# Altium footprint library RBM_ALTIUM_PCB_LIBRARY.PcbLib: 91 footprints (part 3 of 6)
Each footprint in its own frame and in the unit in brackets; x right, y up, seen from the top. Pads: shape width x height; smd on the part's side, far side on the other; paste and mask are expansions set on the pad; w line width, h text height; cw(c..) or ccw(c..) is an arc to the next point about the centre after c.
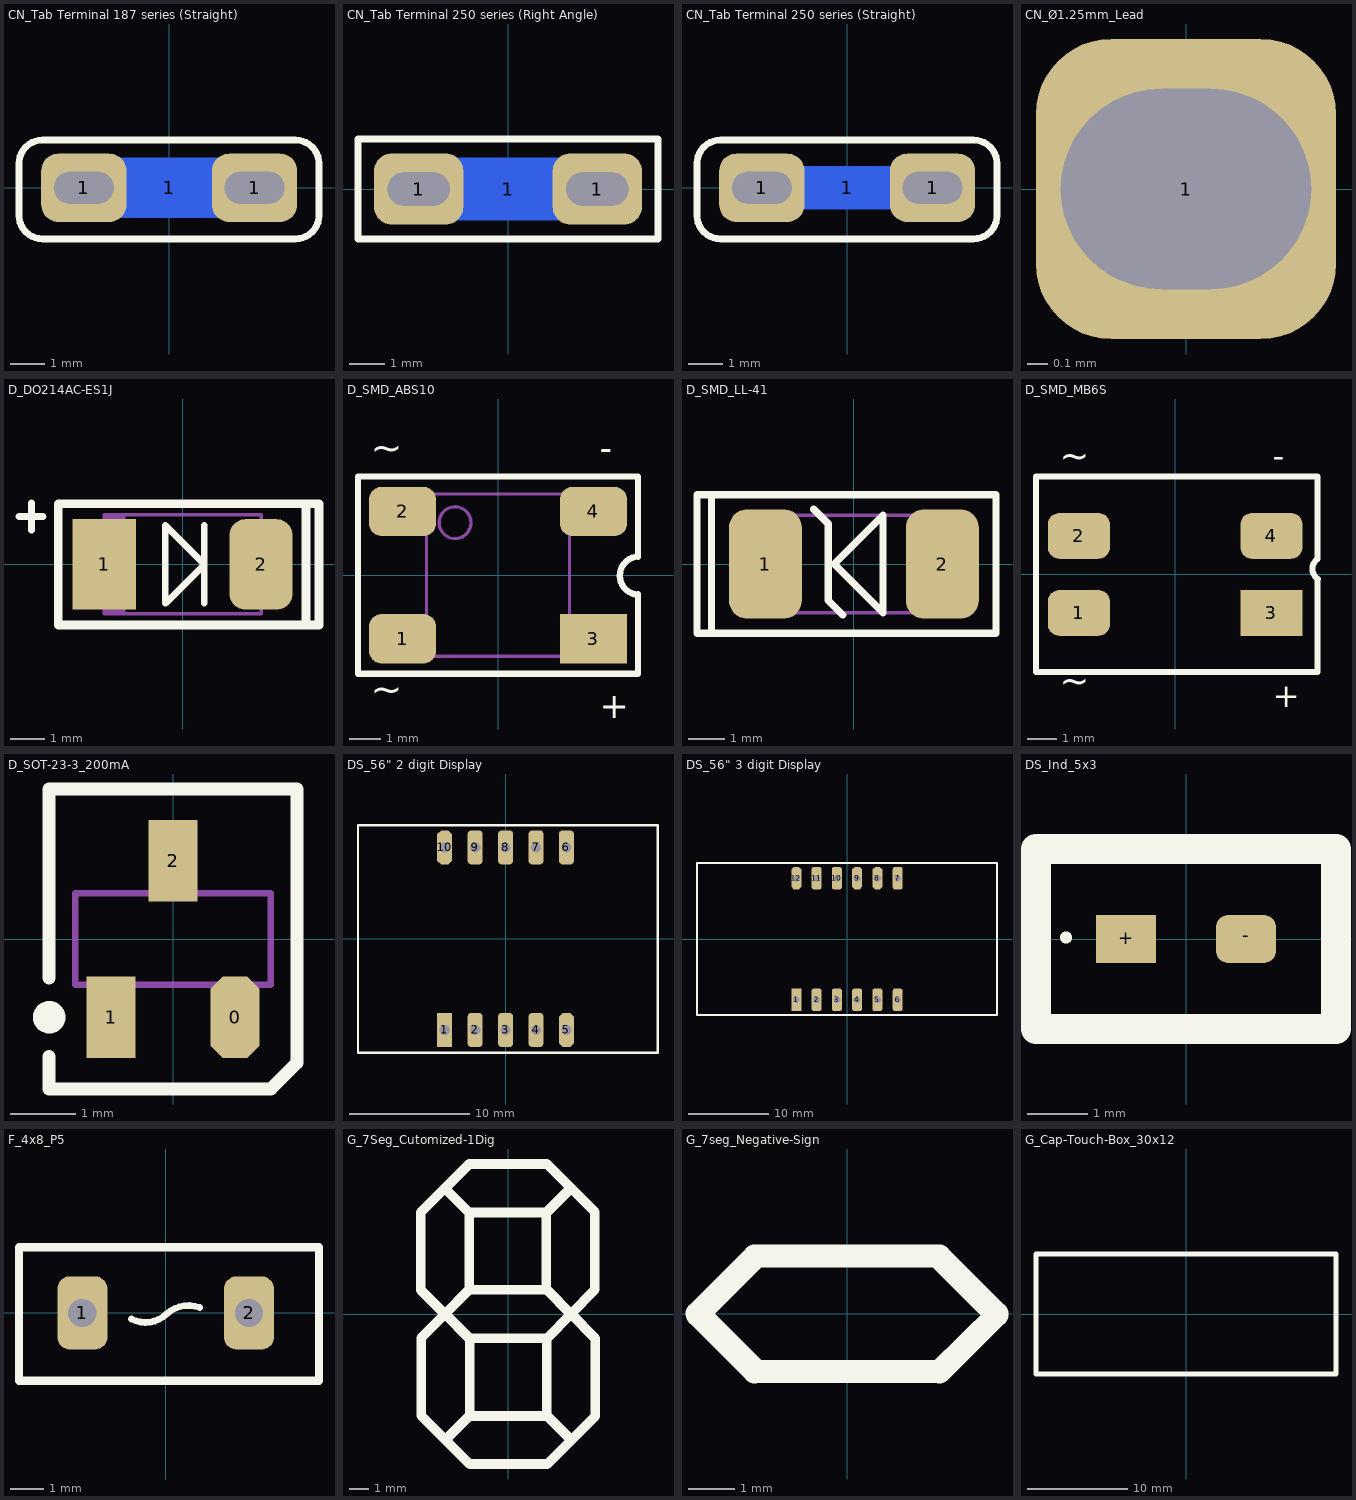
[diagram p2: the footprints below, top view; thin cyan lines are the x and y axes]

## CN_Tab Terminal 187 series (Straight) [mm]
pads (3):
  rrect50% 2.5x2 hole 0.95 slot 1.75 at 0 deg: 1(-2.5,0) 1(2.5,0)
  rect 2.85x1.75 smd far side: 1(0,0)
Top Overlay:
  lines w0.2: -4.4,-0.81 ccw(c-3.712,-0.81) -3.712,-1.498 3.7,-1.497 ccw(c3.7,-0.81) 4.388,-0.81 ; -4.4,-0.8 -4.4,0.712 ; -4.4,0.71 cw(c-3.712,0.71) -3.712,1.398 ; -3.712,1.397 3.7,1.397 ; 3.7,1.398 cw(c3.7,0.71) 4.388,0.71 ; 4.388,-0.812 4.388,0.7
3D body "4.8mm PCB Tab Terminal (Straight).stp": height 9, standoff -3.45, extent -3.962,-1.3 3.962,1.494

## CN_Tab Terminal 250 series (Right Angle) [mm]
pads (3):
  rrect50% 2.5x2 hole 0.95 slot 1.75 at 0 deg: 1(-2.5,0) 1(2.5,0)
  rect 2.85x1.75 smd far side: 1(0,0)
Top Overlay:
  lines w0.2: -4.2,-1.397 4.2,-1.397 4.2,1.397 -4.2,1.397 -4.2,-1.397
3D body "6.3mm PCB Tab Terminal (Right Angle).STEP": height 9.1, standoff -2.9, extent -4,-0.4 12.2,0.4

## CN_Tab Terminal 250 series (Straight) [mm]
pads (3):
  rrect50% 2.5x2 hole 0.95 slot 1.75 at 0 deg: 1(-2.5,0) 1(2.5,0)
  rect 2.85x1.25 smd far side: 1(0,0)
Top Overlay:
  lines w0.2: -4.4,-0.81 ccw(c-3.712,-0.81) -3.712,-1.498 3.7,-1.497 ccw(c3.7,-0.81) 4.388,-0.81 ; -4.4,-0.8 -4.4,0.712 ; -4.4,0.71 cw(c-3.712,0.71) -3.712,1.398 ; -3.712,1.397 3.7,1.397 ; 3.7,1.398 cw(c3.7,0.71) 4.388,0.71 ; 4.388,-0.812 4.388,0.7
3D body "6.3mm PCB Tab Terminal (Straight).stp": height 10.2, standoff -3.8, extent -4,-0.4 4,0.4

## CN_Ø1.25mm_Lead [mm] "Lead Wire"
pads (1):
  rrect50% 1.5x1.5 / inner rrect50% 1.5x1.5 / far side rrect50% 2.5x1.5 hole 1.25 slot 1 at 90 deg: 1(0,0)

## D_DO214AC-ES1J [mm] "Molded Diode, 2-Leads, Body 4.29x2.69mm, IPC Medium Density"
height 2.44
pads (2):
  rect 1.85x2.65 smd: 1(-2.3,0)
  rrect50% 1.85x2.65 smd: 2(2.3,0)
Top Overlay:
  lines w0.2: -4.8,1.4 -4.1,1.4 ; -4.435,1 -4.435,1.8 ; 0.635,-1.143 0.635,1.143 ; -0.508,-1.143 -0.508,1.143 0.635,0 -0.508,-1.143
  lines w0.254: 3.619,-1.778 3.619,1.778 ; -3.65,-1.778 -3.65,1.778 4,1.778 4,-1.778 -3.65,-1.778
Mechanical 13:
  rectangle: -2.3,-1.45 -1.681,1.45
  lines w0.1: -2.3,-1.45 -2.3,1.45 2.3,1.45 2.3,-1.45 -2.3,-1.45
3D body "DIOM4327X24N.step": height 2.44, standoff 0, extent -2.52,-1.45 2.52,1.45

## D_SMD_ABS10 [mm]
pads (4):
  rrect50% 2.1x1.55 smd: 1(-3,-2) 2(-3,2) 4(3,2)
  rect 2.1x1.55 smd: 3(3,-2)
Top Overlay:
  lines w0.2: 4.299,-0.603 cw(c4.427,-0.017) 4.306,0.57 ; 4.4,-0.603 4.4,-3.1 -4.4,-3.1 -4.4,3.1 4.4,3.1 4.4,0.57
  text "~" at -4,3.3 h1.5
  text "+" at 3.2,-3.8 h0.8
  text "-" at 3.2,4.2 h0.8
  text "~" at -4,-4.3 h1.5
Mechanical 13:
  circle w0.1: c-1.35,1.65 r0.5
  lines w0.1: -2.25,-2.55 2.25,-2.55 2.25,2.55 -2.25,2.55 -2.25,-2.55
3D body "TSOP400P650X160-4N.step": height 1.6, standoff 0, extent -3.25,-2.55 3.25,2.55

## D_SMD_LL-41 [mm]
height 2.67
pads (2):
  rrect50% 2x3 smd: 1(-2.425,0) 2(2.425,0)
Top Overlay:
  lines w0.2: -3.9,-1.8 -3.9,1.8 ; -1.1,1.5 -0.7,1.1 -0.7,-1 -0.3,-1.4 ; -4.3,-1.9 -4.3,1.9 3.9,1.9 3.9,-1.9 -4.3,-1.9 ; -0.535,0 0.8,-1.335 0.8,1.335 -0.535,0
Mechanical 13:
  lines w0.1: -2.75,-1.335 2.75,-1.335 2.75,1.335 -2.75,1.335 -2.75,-1.335
3D body "ZD.step": height 2.46, standoff 0.01, extent -2.575,-1.227 2.575,1.228

## D_SMD_MB6S [mm]
pads (4):
  rrect50% 2.1x1.55 smd: 1(-3.25,-1.3) 2(-3.25,1.3) 4(3.25,1.3)
  rect 2.1x1.55 smd: 3(3.25,-1.3)
Top Overlay:
  lines w0.2: 4.8,-0.153 4.8,-3.3 -4.7,-3.3 -4.7,3.3 4.8,3.3 4.8,0.523 ; 4.813,0.523 ccw(c5.028,0.186) 4.816,-0.153
  text "~" at -3.9,3.3 h1.5
  text "+" at 3.3,-3.8 h0.8
  text "-" at 3.3,4.2 h0.8
  text "~" at -3.9,-4.3 h1.5
3D body "User Library-moste3k.STEP": height 1.45, standoff -0.08, extent -3.447,-2.417 3.453,2.577

## D_SOT-23-3_200mA [mm] "Diodes - General Purpose 100V 200mA 1.25V @ 200mA SOT-23(SOT-23-3) RoHS"
height 1.15
pads (3):
  oct 0.75x1.25 smd: 0(0.95,-1.2)
  rect 0.75x1.25 smd: 1(-0.95,-1.2) 2(0,1.2)
Top Overlay:
  circle w0.25: c-1.9,-1.2 r0.125
  lines w0.2: -1.9,-1.8 -1.9,-2.3 1.5,-2.3 1.9,-1.9 1.9,2.3 -1.9,2.3 -1.9,-0.6
Mechanical 13:
  lines w0.1: -1.5,-0.7 1.5,-0.7 1.5,0.7 -1.5,0.7 -1.5,-0.7
3D body "SOT95P245X115-3N.step": height 1.15, standoff 0, extent -1.5,-1.3 1.5,1.3

## DS_56" 2 digit Display [mm]
pads (10):
  rect 1.25x2.85 hole 0.85: 1(-5.08,-7.62)
  rrect50% 1.25x2.85 hole 0.85: 2(-2.54,-7.62) 3(0,-7.62) 4(2.54,-7.62) 6(5.08,7.62) 7(2.54,7.62) 8(0,7.62) 9(-2.54,7.62)
  oct 1.25x2.85 hole 0.85: 5(5.08,-7.62) 10(-5.08,7.62)
Top Overlay:
  lines w0.2: -12.319,-9.525 -12.319,9.475 12.7,9.475 12.7,-9.525 ; -12.28,-9.525 12.72,-9.525
Bottom Overlay:
  text "d" at -4.878,-4.833 h1
  text "dp" at -1.738,-4.9 h1
  text "e" at 0.201,-4.833 h1
  text "c" at 2.742,-4.833 h1
  text "g" at -2.24,4.3 h1
  text "f" at 0.301,4.167 h1
  text "b" at 5.38,4.167 h1
  text "a" at 2.9,4.167 h1
  text "D1" at -4.4,4.1 h1
  text "D2" at 5.8,-5 h1
3D body: height 7, standoff 1, extent -12.3,-9.313 12.719,9.61
3D body: height 7, standoff 1, extent -12.319,-9.525 12.7,9.398
3D body: height 3, standoff -3, extent -2.798,-7.879 -2.28,-7.36
3D body: height 3, standoff -3, extent -0.258,-7.879 0.26,-7.36
3D body: height 3, standoff -3, extent 2.282,-7.879 2.8,-7.36
3D body: height 3, standoff -3, extent 4.822,-7.879 5.34,-7.36
3D body: height 3, standoff -3, extent -5.338,-7.879 -4.82,-7.36
3D body: height 3, standoff -3, extent 4.822,7.361 5.34,7.88
3D body: height 3, standoff -3, extent 2.282,7.361 2.8,7.88
3D body: height 3, standoff -3, extent -0.258,7.361 0.26,7.88
3D body: height 3, standoff -3, extent -2.798,7.361 -2.28,7.88
3D body: height 3, standoff -3, extent -5.338,7.361 -4.82,7.88

## DS_56" 3 digit Display [mm]
pads (12):
  rect 1.25x2.85 hole 0.85: 1(-6.35,-7.62)
  rrect50% 1.25x2.85 hole 0.85: 2(-3.81,-7.62) 3(-1.27,-7.62) 4(1.27,-7.62) 5(3.81,-7.62) 6(6.35,-7.62) 7(6.35,7.62) 10(-1.27,7.62) 11(-3.81,7.62)
  oct 1.25x2.85 hole 0.85: 8(3.81,7.62) 9(1.27,7.62) 12(-6.35,7.62)
Top Overlay:
  lines w0.2: -18.796,-9.525 18.796,-9.525 18.796,9.525 -18.796,9.525 -18.796,-9.525
Bottom Overlay:
  text "a" at -3.37,4.3 h1
  text "b" at 6.73,4.2 h1
  text "f" at -1.07,4.3 h1
  text "g" at 4.1,-4.567 h1
  text "c" at 1.6,-4.7 h1
  text "e" at -6.1,-4.767 h1
  text "dp" at -0.5,-4.7 h1
  text "d" at -3.5,-4.8 h1
  text "D3" at 4.64,4.2 h1
  text "D2" at 2.13,4.2 h1
  text "D1" at -5.67,4.2 h1
3D body "User Library-5631_w_o_color_jam.step": height 8.1, standoff -5.5, extent -18.796,-9.525 18.804,9.475

## DS_Ind_5x3 [mm]
pads (2):
  rect 1x0.8 smd: +(-1,0)
  rrect50% 1x0.8 smd: -(1,0)
Top Overlay:
  circle w0.1: c-2,0.025 r0.05
  lines w0.5: -2.5,-1.5 2.5,-1.5 2.5,1.5 -2.5,1.5 -2.5,-1.5
3D body "ALSRobot-LED0603(R).step": height 0.6, standoff 0, extent -0.81,-0.4 0.81,0.4

## F_4x8_P5 [mm]
pads (2):
  rrect50% 1.5x2.2 hole 0.85: 1(-2.5,0) 2(2.5,0)
Top Overlay:
  lines w0.2: -1.028,-0.184 ccw(c-0.609,0.633) 0.034,-0.022 ; 0.001,-0.057 cw(c0.685,-0.753) 1.023,0.162
  lines w0.254: -4.402,-2.032 4.598,-2.032 4.598,1.968 -4.402,1.968 -4.402,-2.032
3D body: height 7, standoff 0.68, extent -4.505,-1.968 4.512,1.968
3D body: height 1.5, standoff -2, extent -2.797,-0.299 -2.199,0.3
3D body: height 1.5, standoff -2, extent 2.203,-0.299 2.801,0.3

## G_7Seg_Cutomized-1Dig [mm]
Top Overlay:
  lines w0.5: -4.475,1.237 -3.237,0 ; -3.263,0 -4.5,1.237 -4.5,5.237 -3.263,6.475 ; -3.237,6.5 -2,7.737 2,7.737 3.237,6.5 4.475,5.263 4.475,1.263 3.237,0.025 ; -3.212,-6.475 -1.975,-5.237 2.025,-5.237 3.263,-6.475 ; -3.212,-6.45 -1.975,-5.212 -1.975,-1.212 -3.212,0.025 ; -2,-7.687 -3.237,-6.45 -4.475,-5.212 -4.475,-1.212 -3.237,0.025 ; -2,-1.212 -3.237,0.025 ; -2,7.712 -3.237,6.475 ; -1.975,-7.712 2.025,-7.712 3.263,-6.475 ; 3.212,0.025 1.975,1.263 1.975,5.263 3.212,6.5 ; 3.237,-6.475 2,-5.237 2,-1.237 ; 3.237,6.475 2,5.237 -2,5.237 ; 3.263,0 4.5,-1.237 4.5,-5.237 3.263,-6.475 ; 4.475,-1.237 3.237,0 ; -3.237,0 -2,1.237 ; -3.237,0 -2,1.237 ; -3.237,0 -2,-1.237 2,-1.237 ; -3.237,0.025 -2,1.263 2,1.263 ; -3.237,6.475 -2,5.237 ; -3.237,6.475 -2,5.237 ; -2,1.237 -2,5.237 ; 2,-1.237 3.237,0 ; 2,-1.237 3.237,0 ; 2,1.263 3.237,0.025 ; 2,1.263 3.237,0.025
3D body: height 8, standoff 0, extent -2.238,7.5 2.25,8
3D body: height 8, standoff 0, extent -3.497,5.003 -1.753,6.747
3D body: height 8, standoff 0, extent -2.238,5 2.25,5.5
3D body: height 8, standoff 0, extent -3.492,6.243 -1.748,7.987
3D body: height 8, standoff 0, extent 1.772,6.235 3.515,7.978
3D body: height 8, standoff 0, extent 1.767,4.994 3.511,6.738
3D body: height 8, standoff 0, extent -4.756,0.962 -4.256,5.45
3D body: height 8, standoff 0, extent -3.503,-0.297 -1.759,1.447
3D body: height 8, standoff 0, extent -2.256,0.962 -1.756,5.45
3D body: height 8, standoff 0, extent -4.743,-0.292 -2.999,1.452
3D body: height 8, standoff 0, extent -4.735,4.972 -2.991,6.715
3D body: height 8, standoff 0, extent -3.494,4.967 -1.75,6.711
3D body: height 8, standoff 0, extent -4.728,-5.438 -4.228,-0.95
3D body: height 8, standoff 0, extent -3.475,-6.697 -1.731,-4.953
3D body: height 8, standoff 0, extent -2.228,-5.438 -1.728,-0.95
3D body: height 8, standoff 0, extent -4.715,-6.692 -2.971,-4.948
3D body: height 8, standoff 0, extent -4.706,-1.428 -2.963,0.315
3D body: height 8, standoff 0, extent -3.466,-1.433 -1.722,0.311
3D body: height 8, standoff 0, extent -2.232,-5.45 2.256,-4.95
3D body: height 8, standoff 0, extent -3.49,-7.947 -1.747,-6.203
3D body: height 8, standoff 0, extent -2.232,-7.95 2.256,-7.45
3D body: height 8, standoff 0, extent -3.486,-6.707 -1.742,-4.963
3D body: height 8, standoff 0, extent 1.778,-6.715 3.522,-4.971
3D body: height 8, standoff 0, extent 1.773,-7.956 3.517,-6.212
3D body: height 8, standoff 0, extent 4.263,-5.45 4.763,-0.962
3D body: height 8, standoff 0, extent 1.765,-1.447 3.509,0.297
3D body: height 8, standoff 0, extent 1.763,-5.45 2.263,-0.962
3D body: height 8, standoff 0, extent 3.006,-1.452 4.749,0.292
3D body: height 8, standoff 0, extent 2.997,-6.715 4.741,-4.972
3D body: height 8, standoff 0, extent 1.757,-6.711 3.501,-4.967
3D body: height 8, standoff 0, extent 4.265,0.956 4.765,5.444
3D body: height 8, standoff 0, extent 1.768,4.959 3.511,6.703
3D body: height 8, standoff 0, extent 1.765,0.956 2.265,5.444
3D body: height 8, standoff 0, extent 3.008,4.954 4.752,6.698
3D body: height 8, standoff 0, extent 3,-0.309 4.743,1.435
3D body: height 8, standoff 0, extent 1.759,-0.305 3.503,1.439
3D body: height 8, standoff 0, extent -2.25,-1.5 2.238,-1
3D body: height 8, standoff 0, extent 1.753,-0.247 3.497,1.497
3D body: height 8, standoff 0, extent -2.25,1 2.238,1.5
3D body: height 8, standoff 0, extent 1.748,-1.487 3.492,0.257
3D body: height 8, standoff 0, extent -3.515,-1.478 -1.772,0.265
3D body: height 8, standoff 0, extent -3.511,-0.238 -1.767,1.506

## G_7seg_Negative-Sign [mm]
Top Overlay:
  lines w0.5: -3.237,0 -2,1.237 ; -3.212,0 -1.975,-1.237 ; -2,-1.263 -3.237,-0.025 -2,1.212 ; 1.975,1.237 3.212,0 ; 2,-1.263 3.25,-0.025 ; 2,-1.25 -2,-1.25 -3.25,0 -2,1.25 2,1.25 3.25,0 ; 2,1.237 3.237,0
3D body: height 8, standoff 0, extent 1.767,-1.506 3.511,0.238
3D body: height 8, standoff 0, extent 1.772,-0.265 3.515,1.478
3D body: height 8, standoff 0, extent -3.492,-0.257 -1.748,1.487
3D body: height 8, standoff 0, extent -2.238,-1.5 2.25,-1
3D body: height 8, standoff 0, extent -3.497,-1.497 -1.753,0.247
3D body: height 8, standoff 0, extent -2.244,1 2.244,1.5

## G_Cap-Touch-Box_30x12 [mm]
Top Overlay:
  lines w0.5: -15,-6 15,-6 15,6 -15,6 -15,-6
3D body: height 8, standoff 0, extent -15.25,-6.206 -14.75,6.207
3D body: height 8, standoff 0, extent -15.206,-6.25 15.207,-5.75
3D body: height 8, standoff 0, extent 14.75,-6.206 15.25,6.207
3D body: height 8, standoff 0, extent -15.206,5.75 15.207,6.25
